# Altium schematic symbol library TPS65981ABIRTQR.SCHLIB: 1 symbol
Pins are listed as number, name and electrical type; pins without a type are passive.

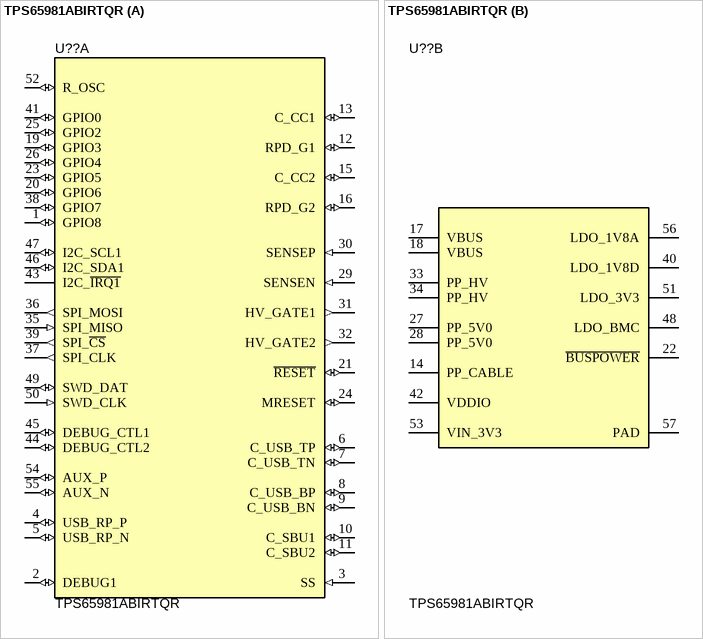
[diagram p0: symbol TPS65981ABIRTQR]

## TPS65981ABIRTQR
designator U??
USB Type-C and USB PD Controller, Power Switch, and High Speed Multiplexer, RTQ0056H; Manufacturer: Texas Instruments; SymbolCreator: Altium; SizeArea_mm2: 64; SizeAreaWB_mm2: 100; SizeX_mm: 8; SizeZ_mm: 1; CompType: IC; U/M: EA
footprint RTQ0056H
part A pins: 1 GPIO8 (io), 2 DEBUG1 (io), 3 SS (in), 4 USB_RP_P (io), 5 USB_RP_N (io), 6 C_USB_TP (io), 7 C_USB_TN (io), 8 C_USB_BP (io), 9 C_USB_BN (io), 10 C_SBU1 (io), 11 C_SBU2 (io), 12 RPD_G1 (io), 13 C_CC1 (io), 15 C_CC2 (io), 16 RPD_G2 (io), 19 GPIO3 (io), 20 GPIO6 (io), 21 ~{RESET} (io), 23 GPIO5 (io), 24 MRESET (io), 25 GPIO2 (io), 26 GPIO4 (io), 29 SENSEN (in), 30 SENSEP (in), 31 HV_GATE1 (out), 32 HV_GATE2 (out), 35 SPI_MISO (in), 36 SPI_MOSI (out), 37 SPI_CLK (out), 38 GPIO7 (io), 39 SPI_~{CS} (out), 41 GPIO0 (io), 43 I2C_~{IRQ1} (oc), 44 DEBUG_CTL2 (io), 45 DEBUG_CTL1 (io), 46 I2C_SDA1 (io), 47 I2C_SCL1 (io), 49 SWD_DAT (io), 50 SWD_CLK (in), 52 R_OSC (io), 54 AUX_P (io), 55 AUX_N (io)
part B pins: 14 PP_CABLE (power), 17 VBUS (power), 18 VBUS (power), 22 ~{BUSPOWER} (power), 27 PP_5V0 (power), 28 PP_5V0 (power), 33 PP_HV (power), 34 PP_HV (power), 40 LDO_1V8D (power), 42 VDDIO (power), 48 LDO_BMC (power), 51 LDO_3V3 (power), 53 VIN_3V3 (power), 56 LDO_1V8A (power), 57 PAD (power)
